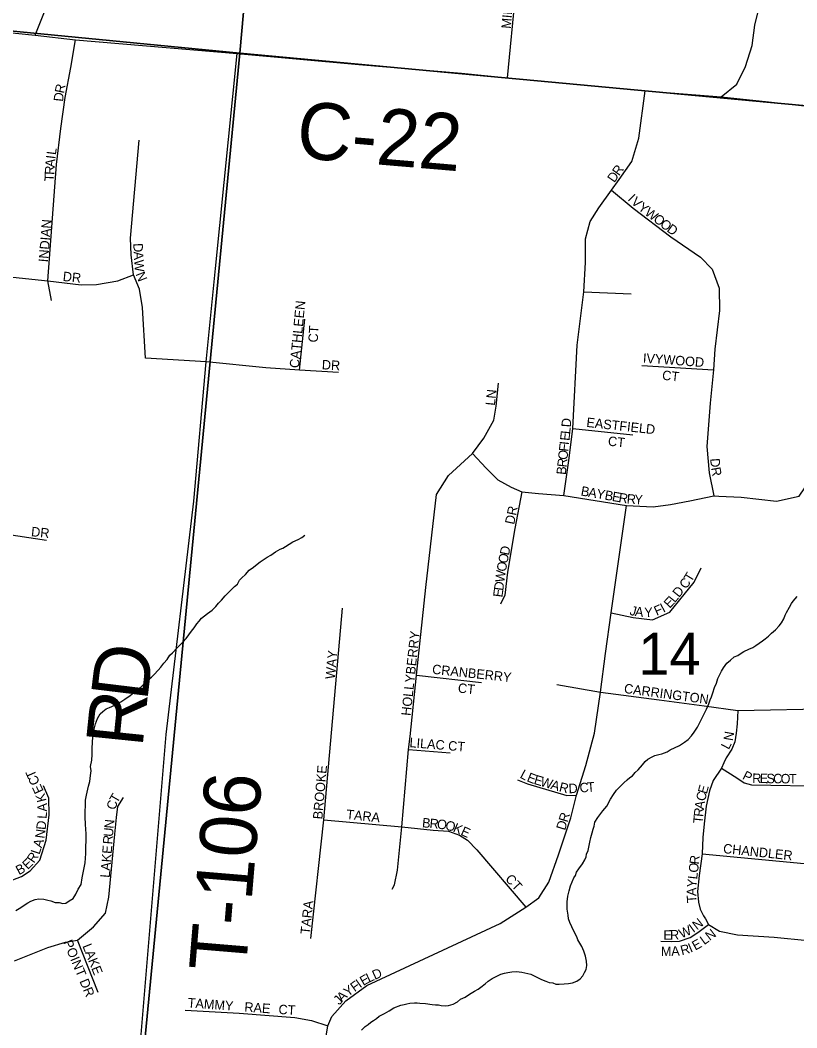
# Model space of a CAD drawing. Extents: x 1310247 to 1552180, y 377264 to 706493.
# Drawn here: x 1403845 to 1407944, y 513107 to 518423 of the extents above; entities that cross this region are included whole.
import ezdxf

# ---------------------------------------------------------------- set-up
doc = ezdxf.new("R2010")
doc.units = 0
for name, color, linetype in [('GM_X_County_Road', 7, 'Continuous'), ('GM_X_County_Road_Text', 7, 'Continuous'), ('GM_X_Minor_River', 7, 'Continuous'), ('GM_X_Section', 7, 'Continuous'), ('GM_X_Section_Text', 7, 'Continuous'), ('GM_X_Township_Road', 7, 'Continuous'), ('GM_X_Township_Road_Text', 7, 'Continuous'), ('GM_X_Township_Subdivision', 7, 'Continuous'), ('GM_X_Township_Subdivision_Text', 7, 'Continuous')]:
    doc.layers.add(name, color=color, linetype=linetype)

msp = doc.modelspace()

# ---------------------------------------------------------------- linework, layer by layer
at = {"layer": 'GM_X_County_Road'}
msp.add_lwpolyline([(1403228.8, 518408.7), (1403479.6, 518388.7), (1403700, 518365.9), (1403924.6, 518343.2), (1404137, 518320), (1404991.5, 518246.5), (1405633.5, 518188.9), (1406174.8, 518143.5), (1406417.5, 518119.1), (1407143.1, 518050.1), (1407545.6, 518017.7), (1407794, 517991.7), (1408079.6, 517960.9), (1408753.3, 517913.8), (1409172.1, 517866.7), (1410071.8, 517802.6)], dxfattribs=at)
at = {"layer": 'GM_X_Minor_River'}
for points in [[(1405054.8, 515521.1), (1405077.1, 515536.7), (1405095.5, 515552.4), (1405111.8, 515566.1), (1405148.3, 515589.4), (1405168.6, 515601), (1405193, 515618.6), (1405217.3, 515632.2), (1405231.5, 515637.9), (1405245.7, 515645.6), (1405284.3, 515670.9), (1405312.6, 515682.4), (1405332.8, 515694), (1405347.1, 515705.8)], [(1403822.6, 513726.3), (1403848.9, 513741.8), (1403867.2, 513753.5), (1403885.5, 513767.2), (1403901.7, 513774.9), (1403923.9, 513784.5), (1403944.1, 513788.1), (1403970.1, 513785.5), (1403992.1, 513781.1), (1404008, 513776.7), (1404029.9, 513768.3), (1404052, 513767.8), (1404069.9, 513763.4), (1404086, 513765.1), (1404104.3, 513776.8), (1404124.5, 513788.4), (1404139, 513812.2), (1404151.6, 513838), (1404168.1, 513863.8), (1404172.8, 513897.8), (1404179.5, 513933.8), (1404188.4, 513977.7), (1404191.3, 514025.8), (1404193.4, 514130.1), (1404190.4, 514180.3), (1404189.1, 514220.5), (1404190.9, 514308.7), (1404195.4, 514334.7), (1404206.4, 514382.6), (1404212.8, 514406.6), (1404217.5, 514438.6), (1404220, 514462.6), (1404216.4, 514484.8), (1404223.1, 514518.7), (1404225.6, 514548.8), (1404226.3, 514582.9), (1404226.9, 514612.9), (1404229.5, 514643), (1404236.3, 514683), (1404242.9, 514710.9), (1404253.4, 514738.8), (1404267.9, 514762.6), (1404282.2, 514776.3), (1404298.5, 514790.1), (1404316.7, 514797.7), (1404345, 514809.2), (1404361.3, 514818.9), (1404377.5, 514826.6), (1404397.8, 514840.2), (1404426.2, 514859.7), (1404452.7, 514881.2), (1404483.3, 514906.7), (1404507.8, 514928.3), (1404524.2, 514946), (1404538.4, 514957.7), (1404552.7, 514971.5), (1404573.2, 514993.1), (1404587.6, 515008.9), (1404604, 515030.6), (1404620.4, 515050.4), (1404634.9, 515072.2), (1404649.2, 515085.9), (1404673.8, 515111.5), (1404706.5, 515142.9), (1404720.9, 515160.7), (1404735.3, 515180.5), (1404749.7, 515200.2), (1404764.1, 515218), (1404778.5, 515237.8), (1404790.8, 515251.6), (1404803.2, 515267.4), (1404833.7, 515292.8), (1404858.1, 515310.4), (1404878.6, 515330), (1404893, 515347.8), (1404907.3, 515363.6), (1404927.8, 515385.2), (1404944.2, 515403), (1404976.9, 515434.4), (1404993.2, 515448.1), (1405003.6, 515468), (1405015.9, 515481.8), (1405034.3, 515499.4), (1405054.8, 515521.1)], [(1406857.8, 514110.3), (1406864.3, 514136.2), (1406868.7, 514154.2), (1406875, 514170.1), (1406877.4, 514192.2), (1406893.9, 514215.9), (1406920.7, 514251.5), (1406941.2, 514277.1), (1406960, 514312.9), (1406976.5, 514338.6), (1406993, 514360.4), (1407013.5, 514382), (1407031.9, 514399.7), (1407048.2, 514415.4), (1407062.5, 514427.2), (1407076.7, 514436.9), (1407091.1, 514454.7), (1407107.4, 514468.4), (1407130, 514494), (1407144.4, 514511.8), (1407158.6, 514523.5), (1407180.9, 514537.1), (1407195.1, 514542.9), (1407215.3, 514548.5), (1407231.4, 514552.2), (1407259.7, 514563.6), (1407275.9, 514573.3), (1407324.5, 514596.4), (1407350.9, 514613.9), (1407371.2, 514627.6), (1407387.6, 514647.3), (1407402, 514667.1), (1407420.6, 514692.8), (1407431, 514714.6), (1407456.1, 514766.3), (1407466.6, 514788.2), (1407479.1, 514816), (1407487.6, 514837.9), (1407493.9, 514853.8), (1407500.3, 514873.7), (1407508.9, 514901.7), (1407519.4, 514925.5), (1407527.9, 514949.4), (1407538.3, 514971.3), (1407546.7, 514989.2), (1407557.1, 515007), (1407575.6, 515030.7), (1407593.9, 515046.4), (1407614.3, 515064), (1407632.5, 515071.7), (1407650.8, 515083.4), (1407665, 515093.1), (1407691.3, 515104.6), (1407711.6, 515114.2), (1407727.8, 515123.9), (1407746.1, 515135.6), (1407762.4, 515149.3), (1407776.6, 515159.1), (1407794.9, 515172.8), (1407811.3, 515188.5), (1407831.7, 515206.1), (1407850.1, 515227.8), (1407862.5, 515243.6), (1407874.9, 515265.4), (1407883.3, 515283.3), (1407889.6, 515297.2), (1407906.2, 515327), (1407916.6, 515344.8), (1407924.9, 515358.7), (1407945.4, 515382.4)], [(1405646.9, 513095.5), (1405665.3, 513113.2), (1405681.5, 513124.9), (1405695.8, 513136.7), (1405710, 513146.4), (1405726.3, 513156.1), (1405740.5, 513167.9), (1405768.9, 513183.4), (1405793.2, 513196.9), (1405817.6, 513212.5), (1405853.9, 513225.8), (1405872.1, 513229.4), (1405886.2, 513233.1), (1405902.3, 513236.8), (1405926.4, 513238.3), (1405940.4, 513238.1), (1405954.4, 513237.8), (1405984.5, 513235.2), (1406020.5, 513230.4), (1406036.5, 513228.1), (1406052.5, 513227.8), (1406066.5, 513225.5), (1406088.5, 513223), (1406106.6, 513224.7), (1406130.8, 513232.2), (1406153.1, 513243.8), (1406169.4, 513257.5), (1406193.7, 513269.1), (1406216, 513284.7), (1406242.4, 513300.2), (1406262.7, 513311.8), (1406276.9, 513321.5), (1406299.3, 513339.1), (1406315.6, 513352.9), (1406335.9, 513366.5), (1406350.1, 513374.2), (1406382.5, 513389.6), (1406400.7, 513395.3), (1406418.8, 513398.9), (1406440.9, 513402.5), (1406465, 513404), (1406479, 513401.7), (1406493, 513401.4), (1406509, 513397.1), (1406524.9, 513392.8), (1406540.9, 513390.4), (1406560.8, 513380), (1406582.6, 513369.5), (1406596.5, 513361.2), (1406620.4, 513352.7), (1406636.3, 513346.4), (1406656.3, 513344), (1406672.2, 513337.6), (1406690.2, 513337.3), (1406716.3, 513338.7), (1406738.4, 513340.3), (1406760.6, 513343.9), (1406782.8, 513353.4), (1406801.1, 513365.1), (1406815.4, 513380.9), (1406823.8, 513398.8), (1406832.1, 513414.6), (1406836.6, 513436.6), (1406835, 513458.7), (1406829.5, 513484.9), (1406820, 513511.2), (1406810.4, 513535.5), (1406798.8, 513553.8), (1406789.1, 513572), (1406783.4, 513586.2), (1406767.9, 513616.6), (1406756.3, 513638.9), (1406746.8, 513663.1), (1406739.1, 513681.3), (1406737.5, 513701.5), (1406732.1, 513733.7), (1406732.9, 513771.8), (1406735.4, 513801.8), (1406742, 513829.8), (1406750.5, 513855.7), (1406759, 513877.6), (1406767.4, 513897.5), (1406775.7, 513911.3), (1406782, 513927.3), (1406794.4, 513945.1), (1406813, 513972.8), (1406825.4, 513992.6), (1406831.7, 514008.5), (1406834, 514022.5), (1406842.4, 514042.4), (1406851.3, 514086.4), (1406857.8, 514110.3)]]:
    msp.add_lwpolyline(points, dxfattribs=at)
at = {"layer": 'GM_X_Section'}
for points in [[(1400210.2, 523974.4), (1405478, 523537.9), (1405004.4, 518248.1), (1399715, 518763.5)], [(1405478, 523537.9), (1410492.1, 523078.2), (1410056.3, 517779.6), (1405004.4, 518248.1)], [(1399715, 518763.5), (1405004.4, 518248.1), (1404461.2, 512601.7), (1399128.9, 513068.6)], [(1405004.4, 518248.1), (1410056.3, 517779.6), (1409601, 512131.4), (1404461.2, 512601.7)]]:
    msp.add_lwpolyline(points, close=True, dxfattribs=at)
at = {"layer": 'GM_X_Township_Road'}
for points in [[(1407545.6, 518017.7), (1407627.5, 518084.6), (1407672.7, 518178.5), (1407708.5, 518289.4), (1407722.4, 518396.4), (1407768.5, 518583.7)], [(1404261.9, 510745.8), (1404348.5, 511597.5), (1404449.7, 512596.1), (1404449, 512650.5), (1404615.3, 514655.2), (1404761.8, 515884.8), (1404826.7, 516620.1), (1404877, 517112.7), (1404991.5, 518246.5)]]:
    msp.add_lwpolyline(points, dxfattribs=at)
at = {"layer": 'GM_X_Township_Subdivision'}
for points in [[(1406417.5, 518119.1), (1406461.3, 518574.4), (1406479.1, 518791.9), (1406498.6, 519007.8), (1406519.7, 519108.5), (1406563.6, 519165.3), (1406665.8, 519267.5), (1406712.9, 519314.6), (1407039.7, 519672.4)], [(1403924.6, 518343.2), (1403977.9, 518475.4), (1404025.1, 518632.5), (1404047.8, 518714), (1404068.2, 518863.1), (1404057.3, 519012.8), (1404023.5, 519149.2)], [(1404010.6, 516944.2), (1403991.7, 517047.4), (1404038, 517661), (1404059.7, 517851.7), (1404082.6, 518015.8), (1404112.8, 518173.9), (1404137, 518320)], [(1406714.7, 515914.7), (1406742.8, 516112.7), (1406761.8, 516268.4), (1406785.7, 516708.5), (1406820, 516990.2), (1406828.2, 517144.4), (1406828.2, 517268.6), (1406854.4, 517360.8), (1406898.9, 517433.6), (1406966.1, 517526.2), (1407006.2, 517581.5), (1407073.5, 517678.1), (1407110, 517801), (1407143.1, 518050.1)], [(1404826.7, 516620.1), (1404506.7, 516639.6), (1404490.5, 516907.2), (1404474.4, 517003.9), (1404442.8, 517079), (1404431.5, 517185), (1404428.1, 517273.2), (1404472.9, 517789.9)], [(1406966.1, 517526.2), (1407079.7, 517431.7), (1407279.4, 517280.7), (1407435.2, 517172), (1407496.9, 517108.7), (1407534.2, 517009.7), (1407535.9, 516891.2), (1407511.5, 516686.6), (1407505, 516577.9), (1407487.2, 516402.6), (1407469.2, 516173.4), (1407482.3, 516035.2), (1407506.6, 515913.8)], [(1402970.3, 517143), (1403057.9, 517147), (1403197.8, 517132.1), (1403586.2, 517090.6), (1403991.7, 517047.4), (1404166.7, 517026.4), (1404249, 517029.3), (1404360.5, 517048.4), (1404442.8, 517079)], [(1406820, 516990.2), (1407070, 516978.8)], [(1405320.2, 516576.3), (1405347.8, 516845.7)], [(1405526.3, 516564.9), (1405320.2, 516576.3), (1405141.6, 516588.4), (1404826.7, 516620.1)], [(1407125.4, 516600.6), (1407505, 516577.9)], [(1407532.9, 515912.4), (1407650.4, 515906.4), (1407837.1, 515885.8), (1407956.6, 515911.9), (1408072.5, 516082.4), (1408247.9, 516319.1), (1408271.9, 516359.8), (1408447.7, 516605.8)], [(1405808.9, 513837.9), (1405821.2, 513860.8), (1405836.4, 513939.2), (1405859.1, 514167.4), (1405895.5, 514574.6), (1405903.3, 514644), (1405937.5, 514968), (1405986.3, 515430.4), (1406042.1, 515921.1), (1406105.6, 516021.2), (1406232.9, 516136.1), (1406293.2, 516217.3), (1406345, 516313.5), (1406358, 516386.4), (1406369.3, 516507.8)], [(1406761.8, 516268.4), (1407078.9, 516236)], [(1406232.9, 516136.1), (1406303.9, 516059.5), (1406365.5, 515997.9), (1406436.5, 515958.6), (1406492.5, 515934.3), (1406580.3, 515925.9), (1406714.7, 515914.7), (1407045.3, 515862.5), (1407185.3, 515855), (1407276.8, 515867.1), (1407379.6, 515887.6), (1407506.6, 515913.8), (1407532.9, 515912.4)], [(1406492.5, 515934.3), (1406456.8, 515740.4), (1406416.9, 515510.3), (1406402.9, 515389.1), (1406380, 515342.6)], [(1405404.5, 512500.5), (1405430.7, 512743.3), (1405443.8, 512918.9), (1405462.4, 513073.9), (1405469.9, 513116.9), (1405490.2, 513166.2), (1405564.6, 513249.5), (1405675.3, 513329.8), (1406379.4, 513657.6), (1406513.9, 513743.5), (1406583, 513792.1), (1406635.2, 513876.1), (1406685.7, 514019.9), (1406751.1, 514214.2), (1406780.9, 514335.2), (1406831.4, 514490.2), (1406877.1, 514662), (1406908.9, 514878.2), (1406935, 515081.8), (1406964, 515296.6), (1407045.3, 515862.5)], [(1403458.2, 515758.7), (1403983.8, 515679.1)], [(1406964, 515296.6), (1407081, 515271), (1407182.8, 515259.8), (1407274.5, 515299.3), (1407401.6, 515457.4), (1407439.2, 515533)], [(1405379.3, 513577.8), (1405447.5, 514205), (1405546, 515321.1)], [(1405937.5, 514968), (1406279.8, 514929.4)], [(1406678.2, 514918.9), (1406908.9, 514878.2), (1407217, 514838.1), (1407456, 514806.3), (1407632.5, 514780.7), (1408148, 514791.4)], [(1407632.5, 514780.7), (1407629, 514711.4), (1407623.5, 514661.8), (1407616.9, 514616.4), (1407601.2, 514577.7), (1407571.6, 514530.9), (1407558.3, 514504.1), (1407546.9, 514477), (1407501.8, 514411.3), (1407484.1, 514358), (1407466.3, 514276.8), (1407456, 514182.5), (1407447.6, 514111.5), (1407443.9, 514024.9), (1407429.3, 513910.9), (1407420, 513826.1), (1407424.4, 513769.7), (1407434.2, 513733), (1407451.5, 513697.8), (1407461.5, 513681.3), (1407477.5, 513652.7), (1407535.4, 513617.2), (1407630.6, 513597.6), (1407824.9, 513584.5), (1408001.4, 513567.7)], [(1405895.5, 514574.6), (1406114.5, 514558.1)], [(1407546.9, 514477), (1407626.8, 514425), (1407665.5, 514399.4), (1407705.2, 514389.2), (1408115.2, 514382.6)], [(1406469.9, 514414.8), (1406522.3, 514394), (1406730.5, 514333.3), (1406780.9, 514335.2)], [(1403654.9, 513751.4), (1403688.5, 513803.7), (1403724, 513841), (1403761.4, 513870.9), (1403852.9, 513904.5), (1403898.2, 513935.2), (1403950, 513992.3), (1403983.6, 514096.9), (1403998.5, 514231.4), (1403996.7, 514319.2), (1403968.1, 514383.5)], [(1403815.5, 513460.9), (1403991.1, 513530), (1404084.4, 513558.1), (1404147.9, 513569.2), (1404232, 513640.2), (1404295.4, 513712.3), (1404314, 513797), (1404344.9, 514129.2), (1404353.5, 514217.2), (1404360.2, 514274.5), (1404390.6, 514322.4)], [(1405447.5, 514205), (1405859.1, 514167.4), (1406024.9, 514149.2), (1406105.2, 514144.8), (1406164.6, 514122.6), (1406206.6, 514096.7), (1406254.8, 514045.9), (1406513.9, 513743.5)], [(1407443.9, 514024.9), (1408056.4, 513966), (1408517.7, 513922.6)], [(1407225.6, 513563.4), (1407283.4, 513562.4), (1407324.2, 513563.4), (1407381.9, 513584.3), (1407422.2, 513609.6), (1407477.5, 513652.7)], [(1404257.4, 513293.8), (1404147.9, 513569.2)], [(1404715.4, 513200.8), (1405001, 513184.6), (1405294.9, 513161), (1405383.2, 513145.2), (1405469.9, 513116.9)]]:
    msp.add_lwpolyline(points, dxfattribs=at)

# ---------------------------------------------------------------- texts
at = {"layer": 'GM_X_County_Road_Text'}
msp.add_text('C-22', height=300, rotation=355.2074, dxfattribs=at).set_placement((1405296.9, 517698.1))
at = {"layer": 'GM_X_Section_Text'}
msp.add_text('14', height=221, rotation=0, dxfattribs=at).set_placement((1407108, 514969.8))
at = {"layer": 'GM_X_Township_Road_Text'}
for s, rotation, p in [('D', 83.0507, (1404515.6, 514825.6)), ('R', 84.1725, (1404490.7, 514582)), ('T-106', 85.2363, (1405035.3, 513395.6))]:
    msp.add_text(s, height=300, rotation=rotation, dxfattribs=at).set_placement(p)
at = {"layer": 'GM_X_Township_Subdivision_Text'}
for s, rotation, p in [('MINDY', 85.1359, (1406434.4, 518376.4)), ('R', 78.6448, (1404076, 518034)), ('D', 83.9023, (1404071.5, 517991.5)), ('L', 82.4108, (1404033.8, 517710.1)), ('A', 84.5047, (1404026.8, 517645)), ('I', 82.6148, (1404030.9, 517688.4)), ('R', 87.1953, (1404024.9, 517606.1)), ('R', 54.228, (1407006, 517598.3)), ('T', 87.1853, (1404023.2, 517570.9)), ('D', 55.4521, (1406981.2, 517562.3)), ('I', 315.2783, (1407048.7, 517475.9)), ('V', 317.686, (1407066, 517458.8)), ('Y', 322.6995, (1407102.2, 517426.1)), ('W', 322.9982, (1407137.4, 517399.3)), ('INDIAN', 85.3334, (1403992.4, 517144.4)), ('O', 322.9858, (1407183.1, 517364.9)), ('O', 322.99, (1407218.2, 517338.4)), ('D', 324.4295, (1407254.5, 517311.1)), ('D', 273.215, (1404442.2, 517245.3)), ('A', 273.215, (1404444.6, 517201.4)), ('W', 273.2501, (1404447.1, 517157.4)), ('DR', 353.994, (1404068.6, 517047.4)), ('N', 291.0722, (1404453.9, 517083.8)), ('CATHLEEN', 84.5225, (1405316.6, 516585.8)), ('CT', 86.8161, (1405415.7, 516721.4)), ('DR', 356.9887, (1405436.5, 516581)), ('IVYWOOD', 355.797, (1407130.7, 516616.2)), ('CT', 353.6631, (1407231.5, 516526.3)), ('LN', 84.2872, (1406350.6, 516387.8)), ('D', 85.8886, (1406751.1, 516274)), ('EASTFIELD', 353.8302, (1406831.8, 516277.4)), ('L', 84.4529, (1406747.6, 516237.6)), ('I', 83.8728, (1406741.4, 516180.2)), ('E', 83.9128, (1406743.8, 516202.1)), ('CT', 353.6631, (1406945.5, 516178.7)), ('O', 83.9023, (1406733, 516101.4)), ('F', 83.8952, (1406737.7, 516145.2)), ('R', 83.9016, (1406728.8, 516062.1)), ('D', 274.2772, (1407487, 516110)), ('B', 83.8931, (1406724.6, 516022.7)), ('R', 280.2217, (1407490.9, 516060.6)), ('B', 350.0905, (1406801.6, 515915.9)), ('A', 350.0984, (1406840.6, 515909.1)), ('Y', 350.1143, (1406883.9, 515901.5)), ('B', 350.0905, (1406927.3, 515894)), ('E', 350.0886, (1406966.3, 515887.1)), ('R', 350.0905, (1407001, 515881.1)), ('R', 355.4552, (1407045, 515873.6)), ('Y', 357.2232, (1407086.2, 515870.4)), ('DR', 78.1105, (1406452, 515759.6)), ('DR', 353.9946, (1403901.4, 515701)), ('D', 78.6909, (1406424.7, 515596.8)), ('O', 79.4703, (1406408.1, 515510.6)), ('O', 78.6943, (1406416.1, 515553.7)), ('W', 82.2348, (1406400.4, 515454.5)), ('T', 58.5764, (1407386.9, 515455)), ('D', 82.5986, (1406394.8, 515411)), ('C', 51.3244, (1407358.2, 515418.4)), ('E', 82.6039, (1406390.2, 515376.1)), ('D', 51.2634, (1407322.3, 515373.8)), ('I', 28.0207, (1407239.6, 515296.3)), ('E', 46.254, (1407272.8, 515317.1)), ('L', 51.4069, (1407300.4, 515346.3)), ('J', 345.0996, (1407058.9, 515286.8)), ('A', 353.1469, (1407087.7, 515279.7)), ('Y', 1.8864, (1407139.7, 515274.1)), ('F', 24.2888, (1407204.3, 515280.3)), ('HOLLYBERRY', 83.8625, (1405906.2, 514751.1)), ('WAY', 84.8053, (1405505.8, 514944.5)), ('CRANBERRY', 353.9541, (1406017.8, 514975)), ('CT', 353.6631, (1406153.5, 514876.3)), ('CARRINGTON', 352.4071, (1407030, 514873.8)), ('N', 80.239, (1407606.1, 514618.5)), ('LILAC CT', 355.3884, (1405898.7, 514587.9)), ('L', 62.8974, (1407584.9, 514571.8)), ('T', 113.95, (1403934.6, 514436.5)), ('BROOKE', 84.9572, (1405439.8, 514205.3)), ('L', 331.8038, (1406479, 514428.3)), ('E', 338.5156, (1406515.8, 514409)), ('P', 332.2313, (1407652.7, 514421.7)), ('R', 358.9368, (1407708.3, 514399)), ('E', 359.1412, (1407748.1, 514398.2)), ('S', 359.2546, (1407783.4, 514397.7)), ('C', 359.2813, (1407818.6, 514397.3)), ('O', 359.2568, (1407858.2, 514396.8)), ('T', 359.2795, (1407902.2, 514396.2)), ('C', 113.961, (1403950.7, 514400.3)), ('E', 114.5978, (1403970.6, 514356.3)), ('E', 343.4439, (1406553, 514394.5)), ('W', 343.5861, (1406586.8, 514384.5)), ('A', 343.5957, (1406641.7, 514368.3)), ('R', 346.0073, (1406686.2, 514355.3)), ('D', 2.9243, (1406740.6, 514344.1)), ('C', 5.0339, (1406799.7, 514347.7)), ('T', 5.0633, (1406839.2, 514351.2)), ('E', 74.1878, (1407468.4, 514337.6)), ('K', 104.183, (1403984.7, 514304.3)), ('T', 59.9264, (1404357.4, 514288.8)), ('C', 77.6134, (1407460.1, 514299.7)), ('A', 91.2154, (1403987.3, 514248.1)), ('C', 74.4616, (1404348.1, 514253.7)), ('A', 80.9688, (1407453.3, 514257)), ('L', 86.9296, (1403985.3, 514208.9)), ('TARA', 353.9886, (1405564.6, 514209.4)), ('R', 73.5688, (1406733.8, 514188.4)), ('R', 84.4575, (1407449.6, 514218.4)), ('D', 84.4343, (1403979.6, 514149.6)), ('N', 84.67, (1404338.8, 514156.5)), ('B', 354.4791, (1405964.8, 514165.4)), ('R', 354.4549, (1406004.2, 514161.6)), ('O', 354.4904, (1406043.7, 514157.8)), ('O', 345.4389, (1406085.4, 514153.9)), ('K', 336.6522, (1406126.1, 514143.5)), ('D', 72.792, (1406720.6, 514145.7)), ('T', 84.458, (1407446.2, 514183.3)), ('N', 82.2082, (1403973.4, 514103.9)), ('U', 84.6828, (1404334.7, 514112.7)), ('E', 335.7019, (1406166.3, 514126.2)), ('A', 73.1287, (1403958.8, 514053.3)), ('R', 84.6615, (1404331, 514073.3)), ('CHANDLER', 353.9914, (1407553.3, 514029)), ('R', 55.9476, (1403918.2, 513972.4)), ('L', 71.1903, (1403946.8, 514018.2)), ('LAKE', 85.364, (1404317.8, 513897.2)), ('B', 28.7161, (1403839.1, 513911.7)), ('E', 43.8036, (1403885.4, 513939.2)), ('O', 83.5139, (1407422, 513923.4)), ('R', 83.5188, (1407426.9, 513967.2)), ('CT', 312.7108, (1406402.1, 513889.6)), ('L', 83.5256, (1407418, 513888.5)), ('Y', 83.8131, (1407413.3, 513844.8)), ('T', 94.0876, (1407415.4, 513768.1)), ('A', 89.4535, (1407412.9, 513802.1)), ('TARA', 83.9911, (1405373.8, 513598.3)), ('W', 23.8198, (1407335.6, 513577.6)), ('I', 35.882, (1407397.7, 513606.4)), ('N', 38.1006, (1407417.2, 513620.5)), ('E', 1.2296, (1407240.3, 513571.5)), ('R', 1.2418, (1407275.5, 513572.2)), ('N', 37.6027, (1407485, 513564)), ('POINT DR', 292.6197, (1404071.7, 513559)), ('LAKE', 291.8014, (1404173.1, 513539.2)), ('R', 14.8918, (1407337.3, 513490)), ('I', 23.4766, (1407383.3, 513502.8)), ('E', 29.0173, (1407408.3, 513513.9)), ('L', 36.0475, (1407455.4, 513542.4)), ('M', 0.2368, (1407226.8, 513485.5)), ('A', 3.1678, (1407282.4, 513485.8)), ('E', 29.872, (1405655.9, 513327.4)), ('L', 24.9888, (1405685.4, 513344.4)), ('D', 24.6294, (1405717.2, 513359.2)), ('Y', 35.9607, (1405574.8, 513269.1)), ('F', 35.5774, (1405610.4, 513294.9)), ('I', 35.309, (1405639, 513315.3)), ('J', 47.0559, (1405529.7, 513224.6)), ('A', 43.1529, (1405544, 513240.1)), ('TAMMY', 355.6842, (1404728.3, 513215.1)), ('RAE', 355.9127, (1405027.4, 513193.1)), ('CT', 356.8158, (1405207.7, 513179.9))]:
    msp.add_text(s, height=50, rotation=rotation, dxfattribs=at).set_placement(p)

doc.saveas('drawing.dxf')
